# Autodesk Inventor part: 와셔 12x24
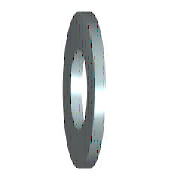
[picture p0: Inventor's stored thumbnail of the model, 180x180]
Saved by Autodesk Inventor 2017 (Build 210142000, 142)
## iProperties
IsCustomPart: 1
Created: 2012-02
Part Number: 와셔 12x24
Material: 스테인리스강
Description: 평면 와셔
Document SubType Name: Modeling
Standard: KS B 1326
Designer: mduedu
Standards Organization: KS
Language: ko-KR
Size Designation: 12x24
Categories: <MemberInstance><Categories><Category DisplayName="조임쇠" InternalName="e4da775c-781d-43d5-af7c-5136215cf5a6" Mnemonic="FSTN"><Category DisplayName="와셔" InternalN
Density: 1 g/cm^3
Appearance: 파란색 - 벽 페인트 - 광택
Author: mduedu
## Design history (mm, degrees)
sketch "스케치"
  geometry: C1 r 12 at (0, 0); C2 r 6.5 at (0, 0); 1 further point
  constraints: 2 centre point, 2 coincident
  dimensions: "d0" = 13 diameter of C2 (= SD1); "d1" = 24 diameter of C1 (= SD2)
extrude "본체" new body sketch "스케치" distance "d2" = 2.5 (= SD); taper "d3" = 0 deg
workaxis "Work Axis1"
workplane "Work Plane1"
body "Solid1"
other parameters: "SD1" = 13 [user parameter; used in 1 equation term], "SD2" = 24 [user parameter; used in 1 equation term], "SD" = 2.5 [user parameter; used in 1 equation term], "d4" = 0, "d5" = 0, "d6" = 0, "d7" = 0, "NND" = 12 [user parameter]
